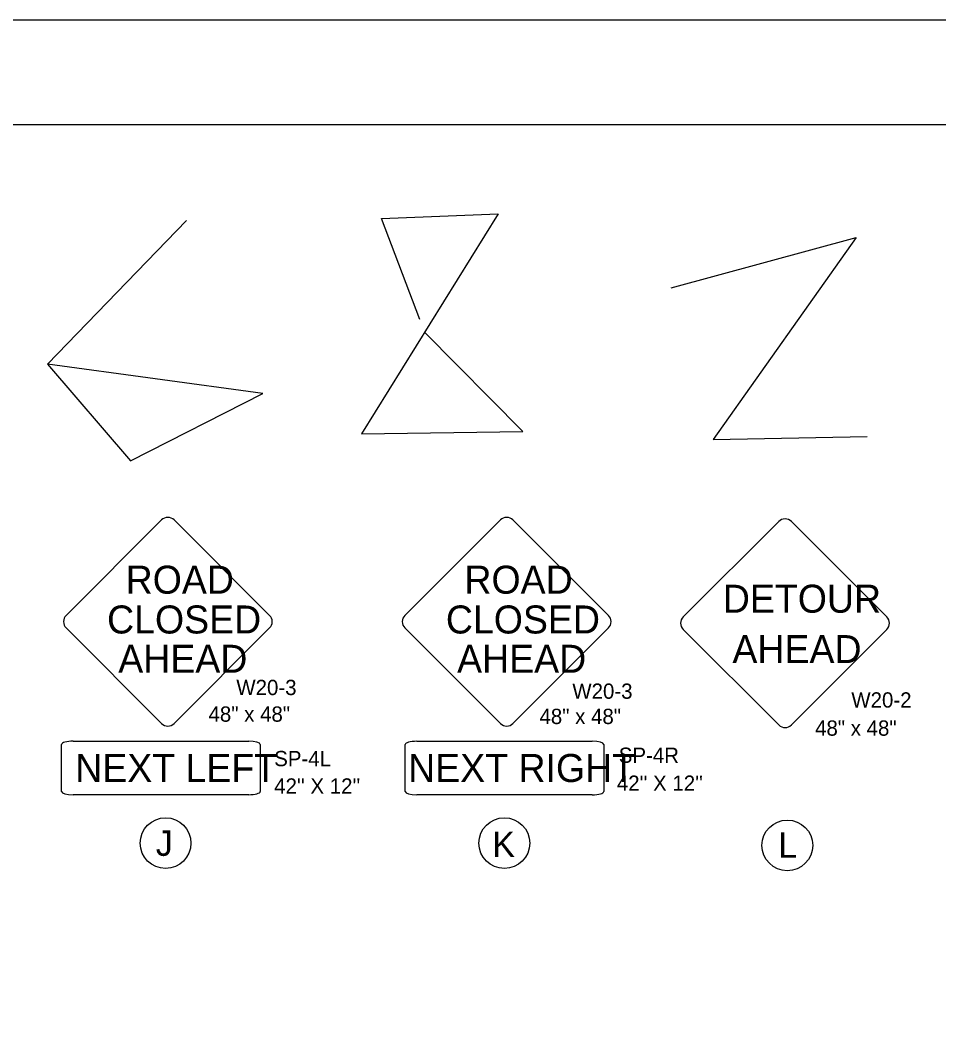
# Model space of a CAD drawing. Extents: x 2157572 to 5059327, y 715220 to 1674494.
# Drawn here: x 2163670 to 2165423, y 729165 to 731089 of the extents above; entities that cross this region are included whole.
import ezdxf

# ---------------------------------------------------------------- set-up
doc = ezdxf.new("R2010")
doc.units = 0
for name, color, linetype in [('Exist Civil Demographics City or Town Circle Label', 7, 'Continuous'), ('Exist Cultural Church Label', 7, 'Continuous'), ('Exist Hydrographic Creek Double Shore Label', 7, 'Continuous'), ('Exist Road Primary Interstate Shield CELL', 7, 'Continuous'), ('Exist Road Secondary Type 20 SR Number Label', 7, 'Continuous'), ('Exist Road Secondary Type 51 Divided Label', 7, 'Continuous'), ('Map Preparation County Base Legend Highway Garage or Maintenance Office', 7, 'Continuous'), ('Map Preparation County North Arrow White Shapes', 7, 'Continuous')]:
    doc.layers.add(name, color=color, linetype=linetype)

msp = doc.modelspace()

# ---------------------------------------------------------------- linework, layer by layer
at = {"layer": 'Exist Civil Demographics City or Town Circle Label'}
for points in [[(2164935.6, 729949.1), (2165117.8, 730131.4)], [(2165141.9, 730131.4), (2165324.2, 729949.1)], [(2165117.8, 729742.8), (2164935.6, 729925.1)], [(2165324.2, 729925.1), (2165141.9, 729742.8)]]:
    msp.add_lwpolyline(points, dxfattribs=at)
for centre, start, end in [((2165129.9, 730119.4), 44.987, 135), ((2164947.6, 729937.1), 135, 225), ((2165312.1, 729937.1), 315, 45), ((2165129.9, 729754.8), 225, 315)]:
    msp.add_arc(centre, 17, start, end, dxfattribs=at)
at = {"layer": 'Exist Cultural Church Label'}
for centre in [(2163947.3, 729517.2), (2164594, 729517.2), (2165134.2, 729512.9)]:
    msp.add_circle(centre, 48.4, dxfattribs=at)
at = {"layer": 'Exist Hydrographic Creek Double Shore Label'}
msp.add_line((2164992.5, 730288.2), (2165286.8, 730293.6), dxfattribs=at)
for points in [[(2164432.4, 730517.3), (2164359.6, 730710.1), (2164582.2, 730718.7), (2164321.1, 730298.8), (2164629.3, 730303.1), (2164441.7, 730492.7)], [(2163987.1, 730705.8), (2163721.7, 730431.6), (2163880.1, 730247.4), (2164132.7, 730375.9), (2163721.7, 730431.6)], [(2164912.2, 730577.4), (2165265.4, 730673.8), (2164992.5, 730288.2)]]:
    msp.add_lwpolyline(points, dxfattribs=at)
at = {"layer": 'Exist Road Primary Interstate Shield CELL'}
msp.add_line((2164128.1, 729705.8), (2164128.1, 729615.6), dxfattribs=at)
for points in [[(2163757.4, 729952.1), (2163939.7, 730134.4)], [(2163963.8, 730134.4), (2164146, 729952.1)], [(2163939.7, 729745.8), (2163757.4, 729928)], [(2164146, 729928), (2163963.8, 729745.8)], [(2163770.9, 729711.8), (2164106, 729711.8)], [(2163748.8, 729615.6), (2163748.8, 729705.8)], [(2164106, 729609.7), (2163770.9, 729609.7)]]:
    msp.add_lwpolyline(points, dxfattribs=at)
for centre, start, end in [((2163951.7, 730122.3), 44.987, 135), ((2163769.5, 729940.1), 135, 225), ((2164134, 729940.1), 315, 45), ((2163951.7, 729757.8), 225, 315)]:
    msp.add_arc(centre, 17, start, end, dxfattribs=at)
for centre, major_axis, start_param, end_param in [((2163770.9, 729705.8), (-22.1, 0), 4.712162, 6.283185), ((2164106, 729705.8), (22.1, 0), 0, 1.570796), ((2163770.9, 729615.6), (-22.1, 0), 0, 1.570796), ((2164106, 729615.6), (-22.1, 0), 1.570796, 3.141593)]:
    msp.add_ellipse(centre, major_axis=major_axis, ratio=0.269231, start_param=start_param, end_param=end_param, dxfattribs=at)
at = {"layer": 'Exist Road Secondary Type 20 SR Number Label'}
msp.add_line((2164426.8, 729711.7), (2164761.9, 729711.7), dxfattribs=at)
for points in [[(2164404.2, 729952.1), (2164586.4, 730134.4)], [(2164610.5, 730134.4), (2164792.8, 729952.1)], [(2164586.4, 729745.8), (2164404.2, 729928)], [(2164792.8, 729928), (2164610.5, 729745.8)], [(2164404.7, 729615.5), (2164404.7, 729705.7)], [(2164784, 729705.7), (2164784, 729615.5)], [(2164761.9, 729609.5), (2164426.8, 729609.5)]]:
    msp.add_lwpolyline(points, dxfattribs=at)
for centre, start, end in [((2164598.5, 730122.3), 44.987, 135), ((2164416.2, 729940.1), 135, 225), ((2164780.7, 729940.1), 315, 45), ((2164598.5, 729757.8), 225, 315)]:
    msp.add_arc(centre, 17, start, end, dxfattribs=at)
for centre, major_axis, start_param, end_param in [((2164426.8, 729705.7), (-22.1, 0), 4.712162, 6.283185), ((2164761.9, 729705.7), (22.1, 0), 0, 1.570796), ((2164426.8, 729615.5), (-22.1, 0), 0, 1.570796), ((2164761.9, 729615.5), (-22.1, 0), 1.570796, 3.141593)]:
    msp.add_ellipse(centre, major_axis=major_axis, ratio=0.269231, start_param=start_param, end_param=end_param, dxfattribs=at)
at = {"layer": 'Exist Road Secondary Type 51 Divided Label'}
msp.add_lwpolyline([(2157571.9, 722288.7), (2171075.9, 722288.7), (2171075.9, 731088.6), (2157571.9, 731088.6)], close=True, dxfattribs=at)
at = {"layer": 'Map Preparation County Base Legend Highway Garage or Maintenance Office'}
for centre in [(2163947.3, 729517.2), (2164594, 729517.2), (2165134.2, 729512.9)]:
    msp.add_circle(centre, 48.4, dxfattribs=at)
at = {"layer": 'Map Preparation County North Arrow White Shapes'}
msp.add_lwpolyline([(2170875.9, 730888.7), (2158875.9, 730888.7), (2158875.9, 722488.7), (2170875.9, 722488.7)], close=True, dxfattribs=at)

# ---------------------------------------------------------------- texts
at = {"layer": 'Exist Civil Demographics City or Town Circle Label'}
for s, height, p in [('DETOUR', 53.5, (2165011.1, 729957.2)), ('AHEAD', 53.5, (2165029.4, 729861)), ('W20-2', 29.18, (2165256.4, 729776)), ('48" x 48"', 29.18, (2165187.2, 729722.3))]:
    msp.add_text(s, height=height, dxfattribs=at).set_placement(p)
at = {"layer": 'Exist Cultural Church Label'}
for s, p in [('J', (2163928.7, 729492.9)), ('K', (2164570.9, 729490.8)), ('L', (2165117, 729489.2))]:
    msp.add_text(s, height=48.6, dxfattribs=at).set_placement(p)
at = {"layer": 'Exist Road Primary Interstate Shield CELL'}
for s, height, p in [('ROAD', 53.5, (2163871.1, 729993.5)), ('CLOSED', 53.5, (2163835.6, 729917.5)), ('AHEAD', 53.5, (2163857, 729842.5)), ('W20-3', 29.18, (2164082.4, 729799.9)), ('48" x 48"', 29.18, (2164029.3, 729749)), ('SP-4L', 29.18, (2164154.7, 729664.1)), ('NEXT LEFT', 53.5, (2163774.8, 729634)), ("42'' X 12''", 29.18, (2164154.7, 729611.7))]:
    msp.add_text(s, height=height, dxfattribs=at).set_placement(p)
at = {"layer": 'Exist Road Secondary Type 20 SR Number Label'}
for s, height, p in [('ROAD', 53.5, (2164517.8, 729993.5)), ('CLOSED', 53.5, (2164482.4, 729917.5)), ('AHEAD', 53.5, (2164503.8, 729842.5)), ('W20-3', 29.18, (2164723.8, 729792.8)), ('48" x 48"', 29.18, (2164661.1, 729744.6)), ('SP-4R', 29.18, (2164812.4, 729670.4)), ('NEXT RIGHT', 53.5, (2164410.3, 729633.9)), ("42'' X 12''", 29.18, (2164808.8, 729617.1))]:
    msp.add_text(s, height=height, dxfattribs=at).set_placement(p)

doc.saveas('drawing.dxf')
